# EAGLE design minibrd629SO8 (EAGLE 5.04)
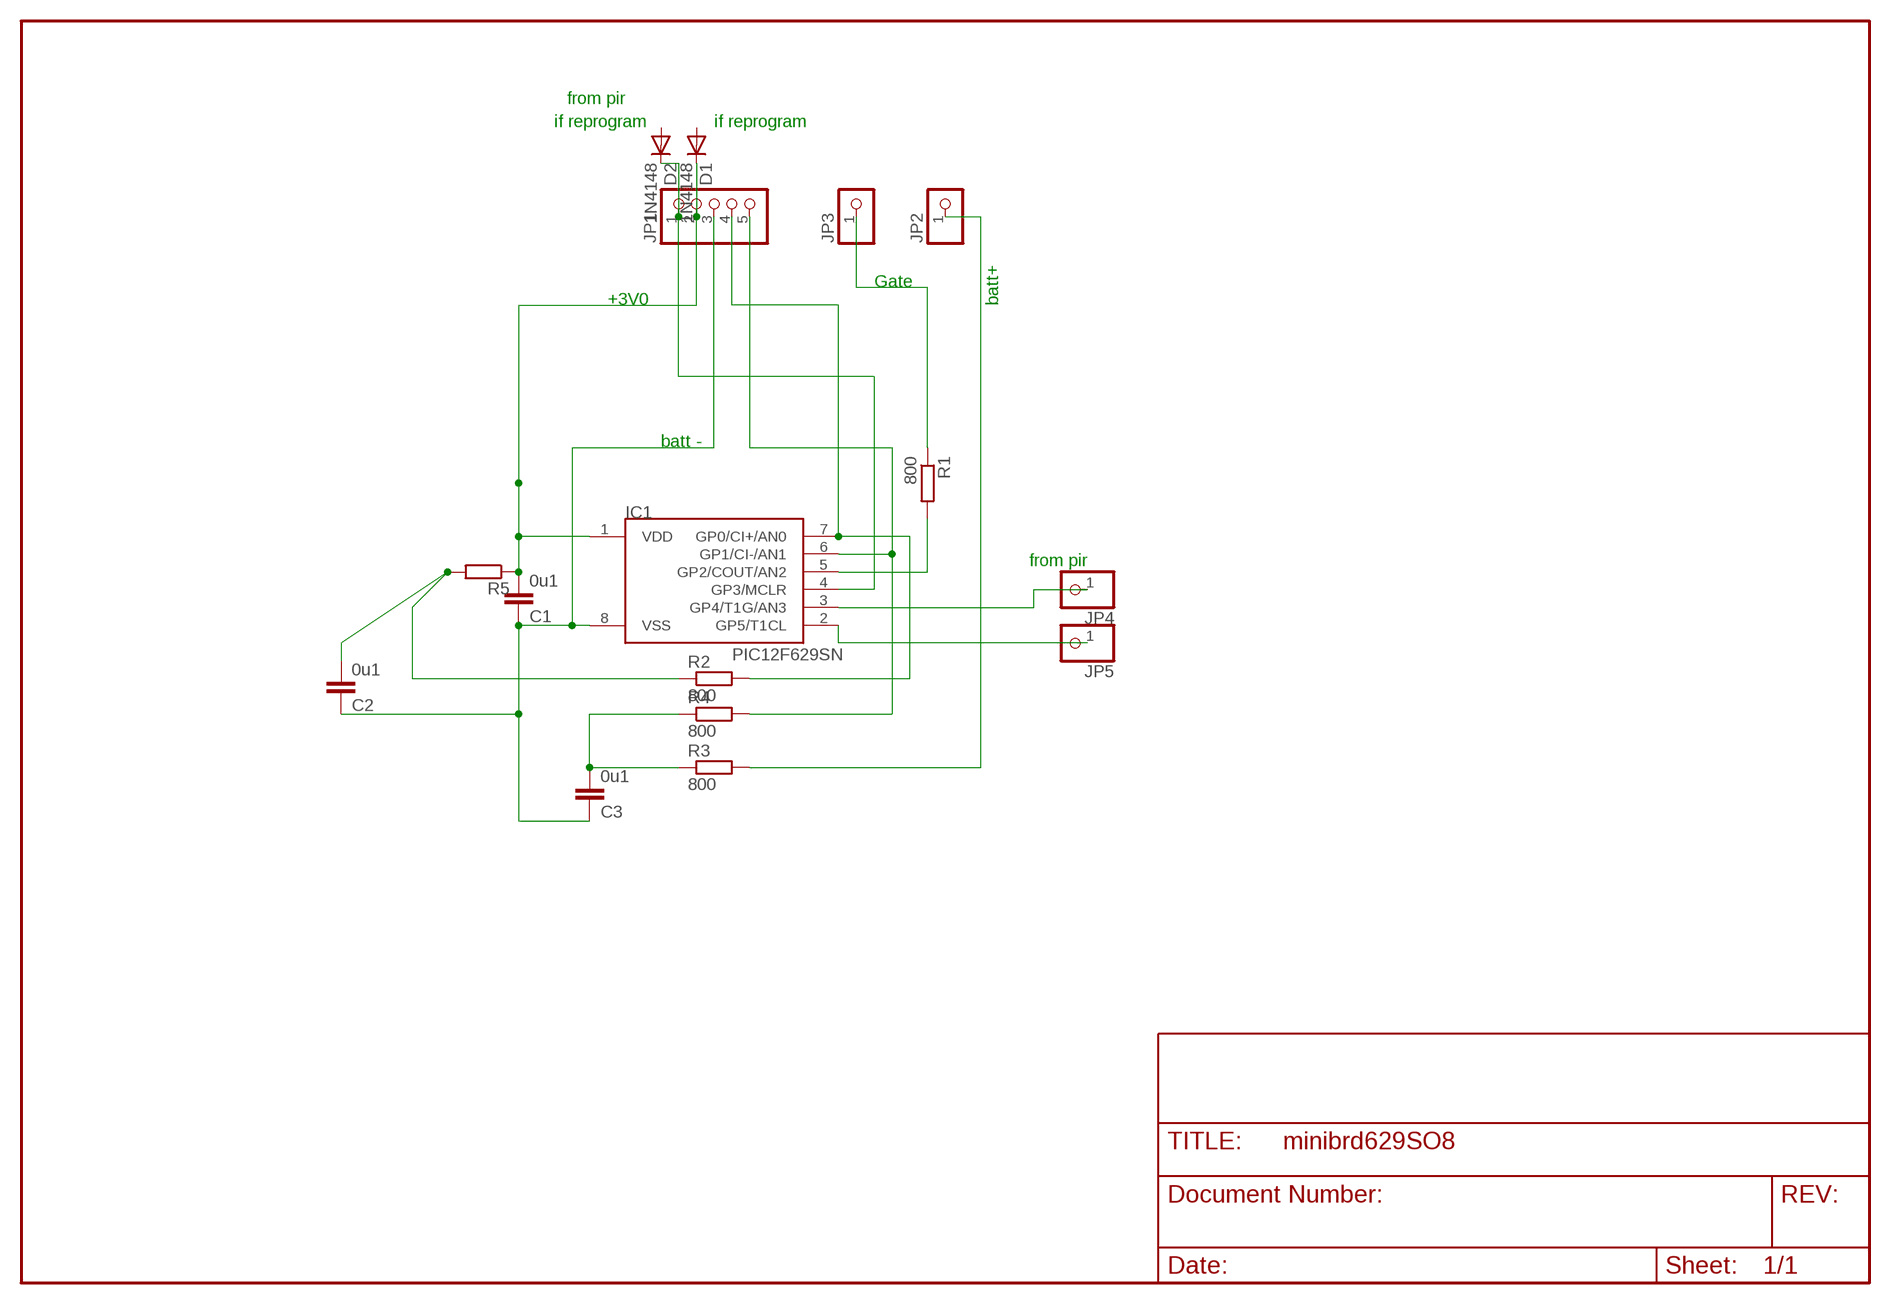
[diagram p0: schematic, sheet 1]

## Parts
C1  0u1  C-EUC1206  [C1206]
C2  0u1  C-EUC1206  [C1206]
C3  0u1  C-EUC1206  [C1206]
D1  1N4148  [DO35-10]
D2  1N4148  [DO35-10]
IC1  PIC12F629SN  [SO-08]
JP1  PINHD-1X5  [1X05]
JP2  PINHD-1X1  [1X01]
JP3  PINHD-1X1  [1X01]
JP4  PINHD-1X1  [1X01]
JP5  PINHD-1X1  [1X01]
R1  800  R-EU_M1206  [M1206]
R2  800  R-EU_M1206  [M1206]
R3  800  R-EU_M1206  [M1206]
R4  800  R-EU_M1206  [M1206]
R5  R-EU_0613/5V  [P0613V]

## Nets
N$1: IC1.5(GP2/COUT/AN2) R1.2
N$4: IC1.7(GP0/CI+/AN0) JP1.4 R2.2
N$5: JP3.1 R1.1
N$6: C2.2 R2.1 R5.2
N$7: C3.2 R3.1 R4.1
N$8: IC1.6(GP1/CI-/AN1) JP1.5 R4.2
N$13: IC1.3(GP4/T1G/AN3) JP4.1
N$14: IC1.2(GP5/T1CL) JP5.1
PIR: D2.C IC1.4(GP3/MCLR) JP1.1
V3: C1.2 D1.C IC1.1(VDD) JP1.2 R5.1
V+: JP2.1 R3.2
V-: C1.1 C2.1 C3.1 IC1.8(VSS) JP1.3
Unconnected: D1.A D2.A

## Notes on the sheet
- from pir
- if reprogram | if reprogram
- Gate
- +3V0 | batt+
- batt -
- from pir

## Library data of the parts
C1-C3 = rcl:C-EU: CAPACITOR, European symbol
D1 D2 = diode-1:1N4148: DIODE
IC1 = microchip-3:PIC12F6*: uPC nW 1k Program Flash memory 2x Timer Comparator 10b A/D converter/ 4xIN
JP1 = pinhead:PINHD-1X5: PIN HEADER
JP2-JP5 = pinhead:PINHD-1X1: PIN HEADER
R1-R5 = rcl:R-EU_: RESISTOR, European symbol

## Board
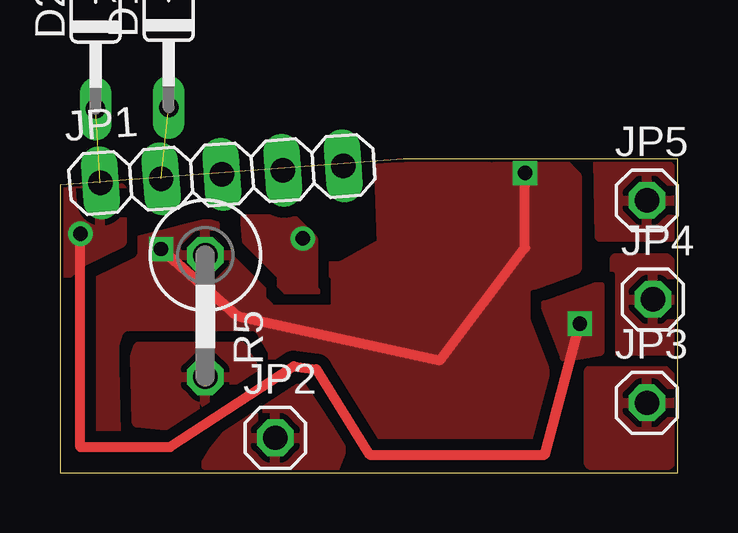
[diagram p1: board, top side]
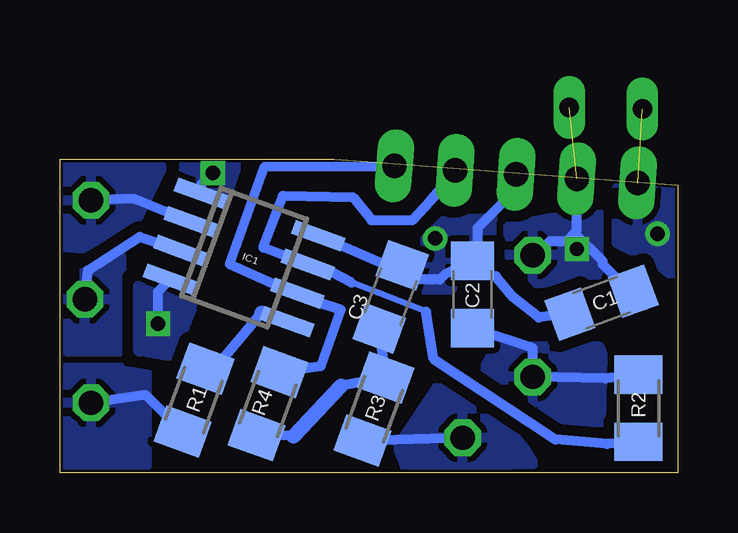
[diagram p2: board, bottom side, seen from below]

Size 25.77 x 13.08 mm. Coordinates in mm from the lower left corner, seen from the top.
Outline: 0,0 25.77,0 25.77,13.07 18,13.07 14.31,13.08 0,11.99 0,0
Copper layers (1*16): Top 0.035mm / dielectric 1.5mm / Bottom 0.035mm
Design rules "default *": minimum track width 10mil, minimum drill 24mil, track to track 18mil, track to pad 18mil, pad to pad 8mil, via to via 8mil, smd to smd 8mil, copper to edge 5mil, drill to drill 8mil, minimum pad ring 10mil, minimum via ring 8mil, stop-mask expansion 4mil, vias tented up to drill 0mil, thermal gap 10mil

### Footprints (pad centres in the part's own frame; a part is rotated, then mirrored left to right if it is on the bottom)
C1206 = smd 1.6 x 1.8: 1 -1.4,0; 2 1.4,0
DO35-10 = drill 0.813 long: A 5.08,0; C -5.08,0
SO-08 = smd 0.6 x 2.2: 1 -1.905,-2.6; 2 -0.635,-2.6; 3 0.635,-2.6; 4 1.905,-2.6; 5 1.905,2.6; 6 0.635,2.6; 7 -0.635,2.6; 8 -1.905,2.6
1X05 = drill 1.016 long: 1 -5.08,0; 2 -2.54,0; 3 0,0; 4 2.54,0; 5 5.08,0
1X01 = drill 1.016 octagon: 1 0,0
M1206 = smd 1.6 x 2: 1 -1.4,0; 2 1.4,0
P0613V = drill 1.016 octagon: 1 -2.54,0; 2 2.54,0

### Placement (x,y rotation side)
C1  3.19,7.09 20 bottom
C2  8.57,7.44 270 bottom
C3  11.98,7.34 250 bottom
D1  4.53,20.32 90 top
D2  1.49,20.25 90 top
IC1  18.09,8.98 250 bottom
JP1  6.75,12.44 4 top
JP2  8.98,1.46 0 top
JP3  24.47,2.92 0 top
JP4  24.73,7.23 0 top
JP5  24.47,11.36 0 top
R1  20.18,3.03 70 bottom
R2  1.64,2.69 270 bottom
R3  12.67,2.65 250 bottom
R4  17.09,2.88 70 bottom
R5  6.06,6.54 270 top

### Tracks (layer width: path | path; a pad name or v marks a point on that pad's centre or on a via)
N$1
  Bottom 0.406: R1.2 19.39,4.25 17.36,6.66
  Bottom 0.61: 17.36,6.66 IC1.5
N$4
  Bottom 0.254: 10.5,6.73 13.61,7.93
  Bottom 0.406: JP1.4 9.42,12.38 10.31,11.36 11.07,10.54 12.79,10.54 13.55,11.49 16.47,11.55 17.3,9.39 IC1.7 15.33,8.63 14.44,8.38 13.61,7.93 | 10.5,6.73 10.19,4.76 5.11,1.39 2.95,1.2 R2.2
N$5
  Bottom 0.406: R1.1 22.2,3.24 JP3.1
  pour Bottom (rank 2): 22.31,4.38 25.49,4.38 25.49,0.31 22.12,0.31 22.12,4.19
  pour Top: 22.06,4.25 25.23,4.25 25.55,3.93 25.55,0.5 25.36,0.31 22.12,0.31 22.06,0.38
N$6
  Bottom 0.406: R2.1 3.01,3.93 R5.2 6.06,5.2 C2.2
  pour Bottom: 3.26,5.27 7.58,5.27 8.15,4.25 4.41,1.96 3.2,2.09 3.14,4.88
  pour Top: 3.26,5.27 7.58,5.27 8.15,4.25 4.41,1.96 3.2,2.09 3.14,4.88
N$7
  Bottom 0.406: C3.2 12.15,3.87 R3.1 14.06,3.61 | R4.1 17.42,1.65 16.03,1.52
  Bottom 0.61: 14.06,3.61 16.03,1.52
N$8
  Bottom 0.406: JP1.5 17.23,12.76 18.69,8.69 16.47,7.68 15.96,7.42 | 15.96,7.42 IC1.6 | 15.96,7.42 14.06,6.79 14.88,4.44 16.73,4.19 R4.2
N$13
  Bottom 0.406: IC1.3 22.44,9.84 24.6,8.44 JP4.1
  pour Bottom (rank 2): 24.03,8.69 25.43,8.06 25.49,5.08 23.2,5.08 23.2,9.01
  pour Top (rank 2): 23.14,8.95 25.3,8.95 25.62,8.63 25.62,5.2 25.49,5.08 23.14,5.08 23.08,5.14
N$14
  Bottom 0.406: IC1.2 22.69,11.42 24.6,11.36 JP5.1
  pour Bottom: 21.49,12.76 22.5,10.66 24.85,9.33 25.55,9.39 25.62,12.82 24.66,12.76
  pour Top: 22.44,13.01 25.17,13.01 25.62,12.57 25.62,9.96 25.49,9.84 22.5,9.84
PIR  (via drill 0.6)  (1 unrouted)
  Top 0.406: v0.85,9.96 0.85,1.07 4.6,1.07 9.74,4.44 10.69,4.31 12.92,0.76 20.22,0.76 v21.68,6.22
  Bottom 0.406: IC1.4 21.19,8.04 21.68,7.55 v21.68,6.22
  pour Bottom: 20.22,6.98 21.04,4.82 22.5,5.08 22.5,7.81 20.79,7.17
  pour Bottom: 0.15,11.81 2.57,11.87 2.57,9.58 0.91,8.76 0.28,8.25 0.09,9.58
  pour Top: 20.22,6.98 21.04,4.82 22.5,5.08 22.5,7.81 20.79,7.17
  pour Top: 0.15,11.81 2.57,11.87 2.57,9.58 0.91,8.76 0.28,8.25 0.09,9.58
V3  (via drill 0.6)  (1 unrouted)
  Top 0.406: v19.39,12.5 19.39,9.39 15.84,4.69 7.39,6.54 v4.22,9.33
  Bottom 0.406: IC1.1 19.88,12.01 v19.39,12.5 | JP1.2 4.22,10.09 4.31,10 | 4.31,10 4.41,9.9 | 4.41,9.9 4.66,9.65 5.36,9.65 6.06,8.95 R5.1 | C1.2 2.01,7.57 3.14,8.69 3.14,8.82 4.31,10 | 4.31,10 | v4.22,9.33 4.22,9.71 4.41,9.9
  pour Bottom: 18.76,11.68 18.38,12.82 20.6,12.82 20.73,12.31
  pour Bottom: 3.33,11.04 3.33,8.25 5.87,7.87 7.07,9.08 7.07,10.28
  pour Top (rank 3): 13.3,13.01 20.92,13.01 21.55,12.38 21.55,8.5 21.36,8.31 21.04,8.31 21.3,0.12 12.28,0.25 7.33,5.96 5.17,5.96 4.47,0.5 0.41,0.5 0.6,9.01 6.38,10.47 7.14,8.82 11.71,8.63 13.42,9.58
V+
  Bottom 0.406: JP2.1 8.92,1.46 R3.2
  pour Bottom: 6.38,1.01 7.2,2.03 9.99,3.68 11.71,1.07 11.39,0.25 5.99,0.38
  pour Top: 6.44,0.95 7.26,1.96 10.06,3.61 11.77,1.01 11.46,0.19 6.06,0.31
V-  (via drill 0.6)
  Bottom 0.406: IC1.8 11.39,8.31 C3.1 11.5,8.61 10.95,8.06 9.93,8.06 9.73,8.26 C2.1 | JP1.3 6.75,11.81 8.34,10.22 8.34,8.44 8.52,8.26 C2.1 | C2.1 7.98,8.26 7.58,8.19 6.87,7.31 5.8,6.47 4.8,6.61 C1.1
  other vias: 10.12,9.77
  pour Bottom (isolate 0.406): 7.65,10.66 9.74,10.66 10.63,9.77 10.63,7.68 10.76,7.55 9.42,7.55 9.17,7.81 9.17,8.19 7.71,9.65
  pour Top (isolate 0.406): 7.65,10.66 9.74,10.66 10.63,9.77 10.63,7.68 10.76,7.55 9.42,7.55 9.17,7.81 9.17,8.19 7.71,9.65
